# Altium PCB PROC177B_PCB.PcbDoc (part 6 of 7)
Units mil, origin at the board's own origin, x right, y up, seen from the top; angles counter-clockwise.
Board outline 4257.98 x 1561.15 mil, 4 copper layers (Top Layer, Int1 (GND), Int2 (PWR), Bottom Layer), stack 63.572 mil thick; 461 components, 307 nets, 1564 pads, 607 vias.
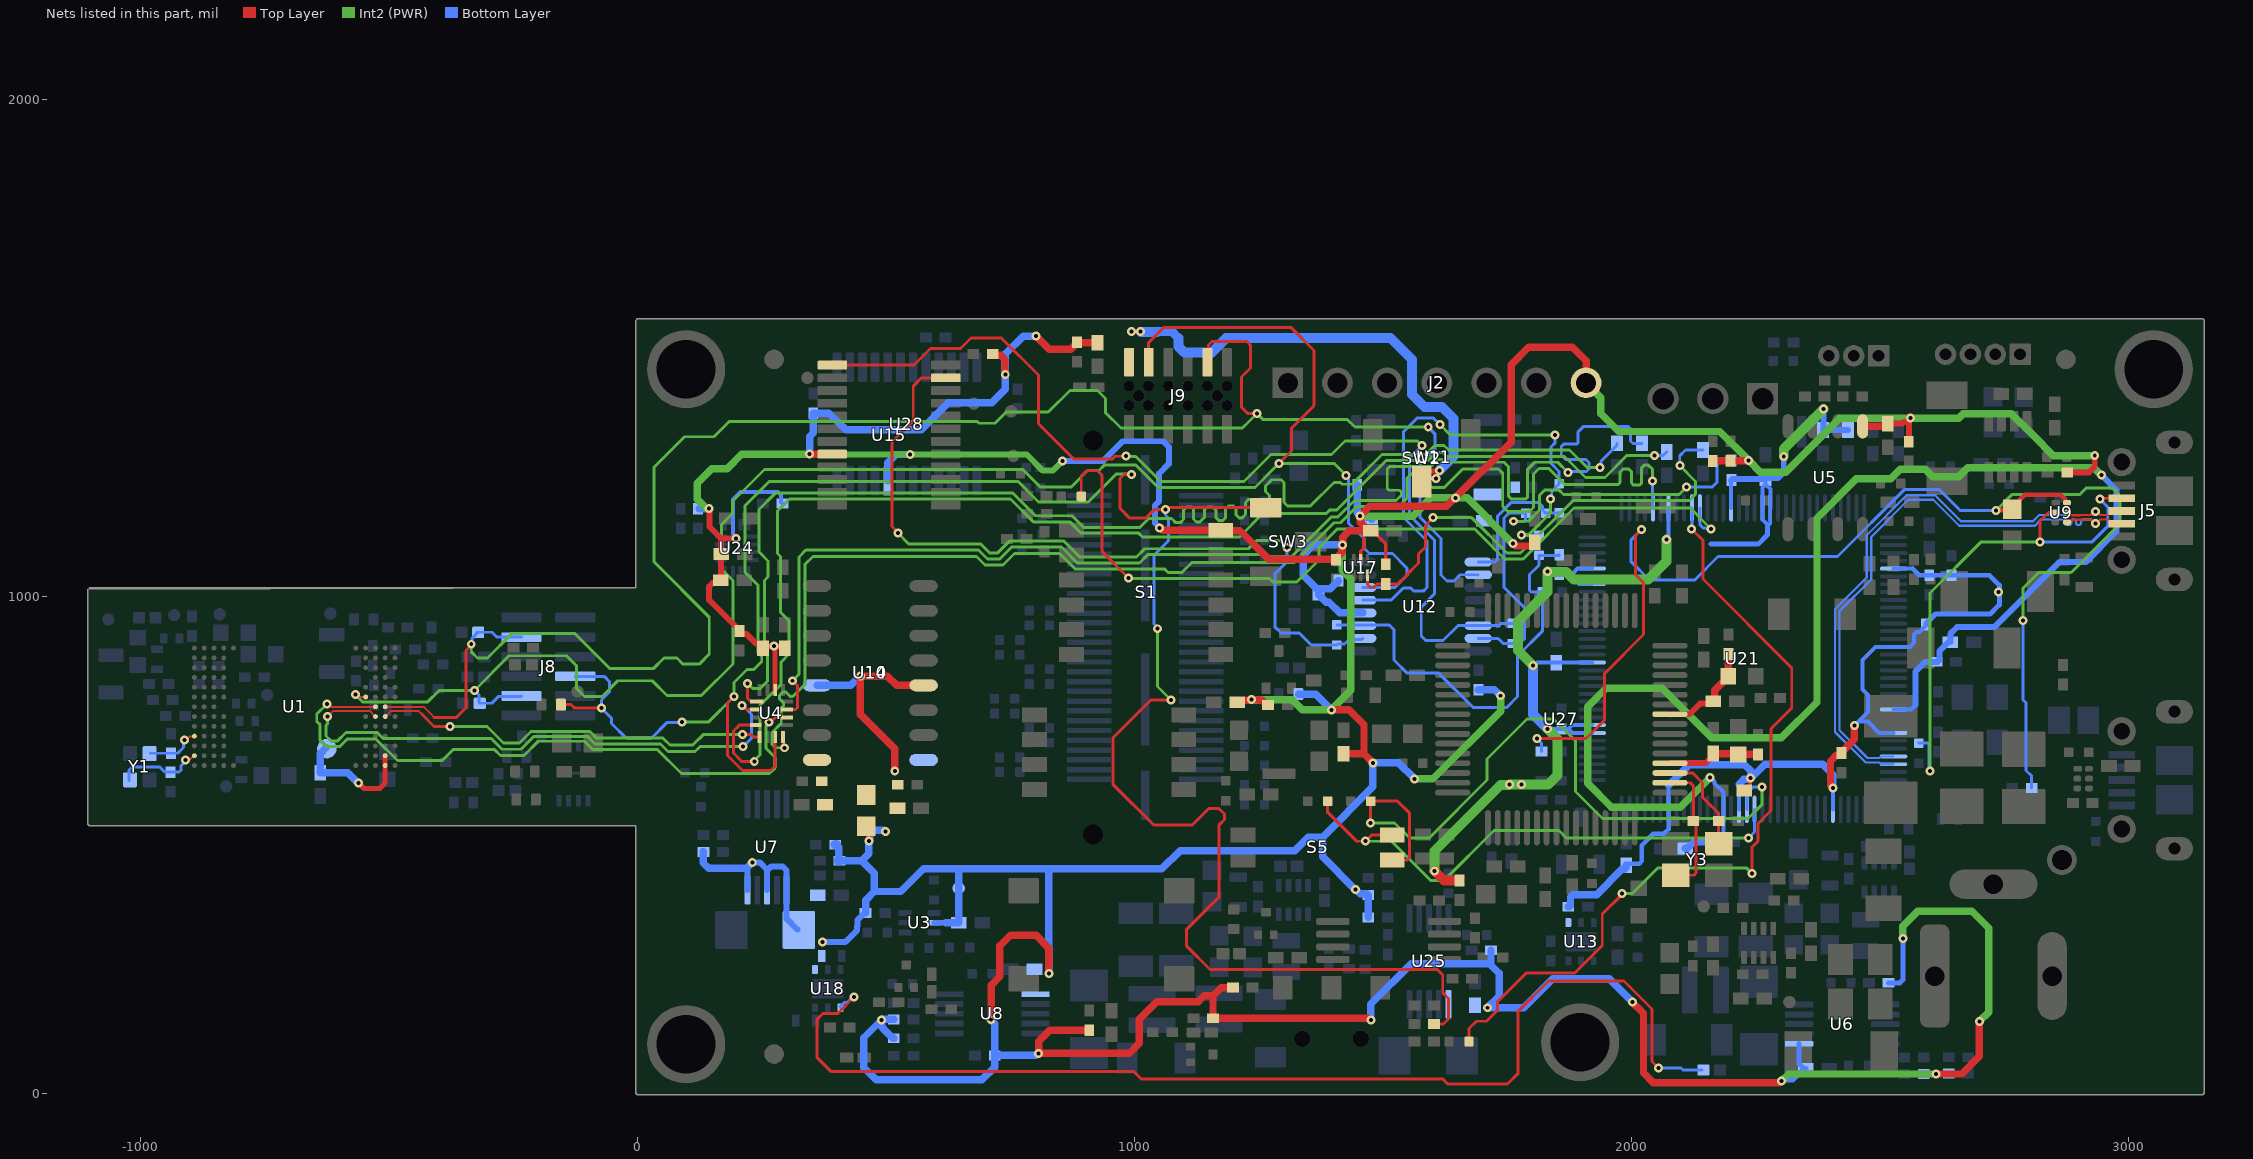
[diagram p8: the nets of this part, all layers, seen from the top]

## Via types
v1: diameter 18, hole 8, Top Layer to Bottom Layer, tented both sides, 603 vias
v2: diameter 19.68, hole 7.87, Top Layer to Bottom Layer, 4 vias

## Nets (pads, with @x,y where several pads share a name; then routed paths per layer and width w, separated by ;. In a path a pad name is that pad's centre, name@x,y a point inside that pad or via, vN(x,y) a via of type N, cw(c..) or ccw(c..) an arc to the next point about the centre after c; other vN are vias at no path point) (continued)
VCC_3V3: C2.1 C36.1 C38.2 C40.1 C41.1 C52.2 C56.1 C57.1 C58.1 C59.1 C65.1 C70.2 C91.1 C133.1 J2.7 R2.2 R5.2 R7.2 R8.2 R12.1 R14.2 R17.2 R22.2 R23.1 R27.2 R28.2 R54.2 R64.2 R65.1 R70.2 R90.1 R94.1 R97.2 R98.2 R99.2 R104.2 R105.2 R106.2 R107.2 R112.1 R115.1 R123.2 R129.1 R135.2 R136.2 R138.2 R142.1 R157.2 R161.2 R165.2 R172.2 R175.2 R198.2 R200.1 R204.2 R213.2 S1.12 TP9.1 U3.5 U4.14 U5.5 U6.6 U7.6 U7.8 U7.10 U8.6 U11.8 U12.12 U15.8 U17.5 U18.1 U24.14 U25.6 U28.8 | length 14993.9
  Top Layer w7: U17.5@1455.43,1073.44 1455.58,1073.59 1455.58,1090.64 1461.36,1096.42 1461.36,1121.59 C52.2@1471.65,1131.87 ; C52.2@1479.52,1131.87 1505.89,1105.51 R138.2@1505.89,1064.06
  Top Layer w10: v1(275.03,899.91) 275.03,897.74 277.72,895.04 U4.14@277.72,811.41
  Top Layer w12: v1(144.96,1176.13) 145.33,1175.76 145.33,1140.27 169.45,1116.14 169.45,1112.91 ; C2.1@168.17,1032 162.36,1026.19 151.58,1026.19 144.55,1019.16 144.55,992.49 201.14,935.9 201.88,935.9 205.72,932.06 205.72,928.61 209.57,924.77 209.57,924.28 219.61,924.28 238.82,905.07 247.28,905.07 253.09,899.26 C91.1@253.09,895.32 256.52,898.76 273.88,898.76 v1(275.03,899.91) 276.17,898.76 293.12,898.76 C40.1@296.84,895.04 ; C2.1@168.54,1032.37 168.54,1084.24 C56.1@168.91,1084.61 ; C56.1@168.61,1084.9 168.61,1116.98 ; 169.34,1116.25 v1(199.22,1116.25) ; R129.1@461,537.11 466.35,531.76 v1(466.35,507.67) ; C38.2@2515.6,1347 2544.07,1347 2547.33,1350.26 2551.54,1350.26 2559.6,1358.32 v1(2561.22,1358.32) ; R22.2@2558.1,1310.59 v1@2558.1,1361.03 ; R17.2@2876.71,1248.69 2920.4,1248.69 2932.2,1260.49 v1(2932.2,1282.82)
  Top Layer w15: v1(346.97,1285.74) U15.8@392.51,1285.74 ; v1@712.83,147.33 v1(712.26,147.91) 712.26,217.6 729.88,235.22 729.88,296.58 751.07,317.76 802.55,317.76 828.16,292.15 v1(828.16,240.96) ; R90.1@715.45,1487.02 717.79,1484.67 731.16,1484.67 739.95,1475.89 739.95,1446.18 v1(740.52,1445.61) ; v1(802.56,1523.02) 829.22,1496.36 872.14,1496.36 884.63,1508.84 R65.1@884.63,1510.81 ; v1(807.01,80.35) 807.29,80.08 989.71,80.08 1010.02,100.38 1010.02,148.61 1045.24,183.82 1128.29,183.82 1140.34,195.87 1158.41,195.87 ; v1@807.59,80.08 807.59,104.42 830.14,126.97 R165.2@909.27,126.97 ; R65.1@885.73,1509.71 R64.2@925.84,1509.71 ; v1(1051.21,1137.2) 1052.83,1137.2 1057.42,1132.62 S1.12@1173.96,1132.62 1174.5,1132.07 1212.67,1132.07 1270.56,1074.18 R123.2@1405.65,1074.18 ; R204.2@1198.46,212.89 1198.24,212.67 1175.21,212.67 1158.41,195.87 ; R70.2@1209.95,785.45 1215.17,790.67 1233.86,790.67 1235.22,792.03 v1(1236.03,792.03) 1236.6,791.46 1251.09,791.46 1252.03,790.51 1257.81,790.51 1267.22,781.11 R172.2@1269.19,781.11 ; v1(1396.67,771.33) 1432.05,771.33 1462.17,741.21 1462.17,683.25 ; R123.2@1405.65,1075.41 1418.2,1087.95 1418.2,1102.66 v1(1418.77,1103.23) 1419.35,1103.8 1419.35,1118.95 1432.27,1131.87 1471.65,1131.87 C52.2@1475.58,1131.87 C52.2@1479.52,1131.87 ; R213.2@1420.9,683.25 1462.17,683.25 ; C52.2@1471.37,1132.15 1454.8,1148.72 1454.8,1160.89 v1(1454.22,1161.46) 1473.26,1180.5 1627.94,1180.5 1645.12,1197.68 v1(1645.93,1197.68) 1757.99,1309.73 1757.99,1465.3 1793.89,1501.2 1880.85,1501.2 1908.83,1473.22 J2.7@1908.83,1429.21 ; v1(1476,147.6) 1475.19,147.6 1471.79,151 R28.2@1158.4,151 1158.4,195.87 ; v1(1480.15,664.54) 1480.15,665.28 1462.17,683.25 ; v1(1761.62,1105.8) 1762.43,1105.8 1767.27,1100.96 1801.12,1100.96 1805.44,1105.27 R99.2@1805.44,1108.25 ; v1(2002.56,183.22) 2002.56,182.48 2024.46,160.57 2024.46,41.17 2044.38,21.25 2297.75,21.25 2301.44,24.94 v1(2302.25,24.94) ; R98.2@2163.94,1272.17 2164.14,1272.37 2199.2,1272.37 R97.2@2199.4,1272.56 2235.53,1272.56 v1(2236.03,1273.05) ; U5.5@2465.27,1341.57 2511.29,1341.57 2515.6,1345.88 C38.2@2515.6,1347 ; v1(2613.08,38.77) 2664.71,38.77 2700.07,74.13 v1@2700.07,143.9
  Int2 (PWR) w12: v1(346.97,1285.74) 347.32,1285.39 v1(549.33,1285.39) 783.17,1285.39 816.06,1252.49 836.17,1252.49 v1(855.83,1272.16)
  Int2 (PWR) w15: v1(144.96,1176.13) 144.38,1176.7 138.95,1176.7 120.93,1194.72 120.93,1227.59 150.04,1256.7 181.26,1256.7 209.95,1285.39 346.61,1285.39 v1(346.97,1285.74) ; v1(1236.03,792.03) 1317.62,792.03 1338.31,771.33 v1(1396.67,771.33) 1435.71,810.38 1435.71,1034.68 1418.77,1051.62 v1(1418.77,1103.23) ; v1(1454.22,1161.46) 1454.75,1160.94 1560.14,1160.94 1596.87,1197.68 v1(1645.93,1197.68) 1669.74,1197.68 v1(1761.62,1105.8) ; v1(1564,632.6) 1600.94,632.6 1736.87,768.53 v1(1736.87,799.7) ; J2.7@1909.04,1429 1938.83,1399.2 1938.83,1367.43 1975.01,1331.25 2177.83,1331.25 v1(2236.03,1273.05) 2259.48,1249.6 2310.84,1249.6 2419.56,1358.32 2658.74,1358.32 2667.82,1367.4 2764.52,1367.4 2809.36,1322.56 2849.09,1282.82 v1(2932.2,1282.82) ; v1@2302.82,25.51 2316.08,38.77 v1(2613.08,38.77) ; v1(2546.09,311.49) 2546.09,336.04 2567.21,357.15 2576,365.94 2685.3,365.94 2718.74,332.51 2718.74,163.38 v1(2700.07,144.71)
  Bottom Layer w8: v1(199.22,1116.25) 199.22,1118.9 192.59,1125.53 192.59,1143.6 U24.14@192.53,1143.67 192.53,1194.13 208,1209.6 283.4,1209.6 289.25,1203.76 289.25,1189.74 R27.2@292.39,1186.6
  Bottom Layer w10: v1(2302.25,24.94) 2303.78,26.47 2324.25,26.47 C57.1@2347.21,49.43 ; U6.6@2337.55,99.67 2337.55,59.09 C57.1@2347.21,49.43 ; C57.1@2351.15,49.43 C57.1@2347.21,49.43 ; R94.1@2517.39,222.27 2540.23,222.27 2546.09,228.12 v1(2546.09,311.49)
  Bottom Layer w11: U3.5@597.22,343.01 621.03,343.01 ; R2.2@2588.39,39.05 2588.53,38.91 2612.94,38.91 v1(2613.08,38.77) 2613.6,39.3 2637.79,39.3 R14.2@2638.31,39.82
  Bottom Layer w12: 219.9,452.98 221.94,450.95 U7.10@221.94,408.58 ; v1(231.57,464.65) 231.61,464.6 246.57,464.6 261.31,449.86 ; U7.8@261.31,408.58 261.31,449.86 ; R200.1@322.65,329.06 300.74,350.97 300.74,408.51 U7.6@300.68,408.58 300.58,408.67 300.58,448.02 291.97,456.63 269.88,456.63 263.11,449.86 261.31,449.86 ; v1(372.96,304.01) 418.41,304.01 442.52,328.12 442.52,336.4 443.03,336.92 443.03,348.11 R54.2@457.7,362.78 ; v1(855.83,1272.16) 937.3,1272.16 976.83,1311.69 1058.06,1311.69 1069.59,1300.16 1069.59,1266.32 1050.06,1246.79 1050.06,1191.12 1041.71,1182.76 1041.71,1147.23 1051.21,1137.73 v1(1051.21,1137.2)
  Bottom Layer w15: R23.1@124.46,1176.13 v1(144.96,1176.13) ; R105.2@133.31,485.6 133.31,463.29 143.62,452.98 219.9,452.98 v1(231.57,464.65) ; v1(346.97,1285.74) 346.97,1321.08 354.19,1328.3 R12.1@354.19,1368.2 385.89,1368.2 419.42,1334.67 571.44,1334.67 625.77,1389 713.18,1389 740.52,1416.34 v1@740.52,1444.8 ; R112.1@400.36,500 405.32,495.05 R104.2@405.32,467.95 ; R104.2@407.13,467.79 451.82,467.79 ; R54.2@459.58,362.69 459.58,388.37 477.11,405.9 ; v1(466.35,507.67) 465.78,507.09 465.78,481.75 451.82,467.79 ; v1@467.91,510.04 467.91,520.03 476.7,528.82 496.36,528.82 498.87,526.31 v1(499.68,526.31) ; v1@493.91,148.6 R106.2@516.31,148.6 ; U28.8@504.26,1232.02 504.35,1232.11 504.35,1268.23 521.17,1285.05 548.99,1285.05 v1(549.33,1285.39) ; R107.2@516.31,110.6 513.97,112.94 512,112.94 494.84,130.11 494.84,130.96 492.08,133.72 492.08,147.23 492.89,148.04 492.08,148.04 v1(491.5,147.46) 456.26,112.22 456.26,51.38 480.76,26.87 693.19,26.87 719.06,52.74 719.06,75.9 R115.1@719.21,76.05 ; 621.03,343.01 646.62,343.01 C36.1@646.86,343.24 TP9.1@646.86,412.49 646.86,451.3 ; v1(712.26,147.91) 712.26,147.1 719.21,140.15 R115.1@719.21,76.05 ; v1(740.52,1445.61) 740.52,1487.24 776.3,1523.02 v1@801.75,1523.02 ; v1(807.01,80.35) 806.2,80.35 801.91,76.05 R115.1@719.21,76.05 ; v1(828.16,240.96) 828.16,451.3 ; R198.2@1330.67,803.03 1364.97,803.03 v1(1396.67,771.33) ; R7.2@1410.82,1031.52 1410.82,1029.55 1408.48,1027.21 1406.51,1027.21 1394.42,1015.11 1375.15,1015.11 C41.1@1370.83,1010.8 ; v1(1418.77,1103.23) 1360.3,1103.23 1339.76,1082.68 1339.76,1041.88 C41.1@1370.83,1010.8 ; v1@1443.77,409.59 1443.77,410.57 1378.81,475.53 1378.81,514.99 ; v1(1444.75,409.59) 1445.56,409.59 1454.09,401.06 1468.15,401.06 R135.2@1470.49,398.71 R136.2@1470.49,353.71 ; v1@1448.43,1168.06 R161.2@1448.43,1223.48 ; v1(1454.22,1161.46) 1455.03,1161.46 1457.64,1158.86 1473.57,1158.86 R175.2@1477.34,1155.09 ; U12.12@1459.67,966.28 1413.19,966.28 1391.78,987.69 1386.07,987.69 1370.83,1002.93 C41.1@1370.83,1006.86 C41.1@1370.83,1010.8 ; v1(1476,147.6) 1476,179.59 1557.09,260.68 1717.68,260.68 ; v1(1564,632.6) 1531.49,665.11 1480.72,665.11 v1(1480.15,664.54) 1480.15,616.33 1378.81,514.99 ; R8.2@1692.31,811.79 1724.66,811.79 1736.75,799.7 v1(1736.87,799.7) ; R142.1@1717.68,287.6 1717.68,260.68 ; v1(2002.56,183.22) 1955.41,230.36 1841.55,230.36 1783.24,172.06 v1(1710.51,172.06) 1734,195.55 1734,241 1717.68,257.32 1717.68,260.68 ; 451.82,467.79 477.11,442.5 477.11,405.9 ; 477.11,405.9 530.6,405.9 575.99,451.3 646.86,451.3 ; 646.86,451.3 828.16,451.3 ; 828.16,451.3 1055.61,451.3 1092.31,488 1322.9,488 1349.89,514.99 1378.81,514.99
  Bottom Layer w20: R112.1@398.71,500 R112.1@400.36,500 ; R104.2@405.32,467.95 405.48,467.79 R104.2@407.13,467.79
VCC_3V3_ENABLE: R9.2 U18.4 | length 2305.4
  Top Layer w5.9: v1(436.38,193.54) 403.47,160.63 374.06,160.63 361.47,148.03 361.47,72.31 389.65,44.13 998.7,44.13 1014.06,28.77 1620.65,28.77 1630.82,18.6 1751,18.6 1771.61,39.22 1771.61,164.02 1833.4,225.81 1985.35,225.81 2041.69,169.47 2041.69,63.91 v1(2055,50.6)
  Bottom Layer w5.9: U18.4@408.92,172.12 408.92,175.07 416.72,182.87 422.43,182.87 433.11,193.54 v1(436.38,193.54) ; v1(2055,50.6) 2100.04,50.6 2104,46.65 R9.2@2142.05,46.65
VCC_LVDS_3V3: C75.1 C88.1 C89.1 C90.1 R129.2 U10.4 U10.16 U14.4 U14.16 | length 450
  Top Layer w15: v1(518.25,648.7) 518.25,693.42 449,762.67 v1(449,839.6) 449.57,839.03 503.39,839.03 521.89,820.53 U14.4@576.39,820.53
  Bottom Layer w15: U10.4@361.83,820.53 429.93,820.53 v1(449,839.6)
VCC_SNSR_BRD: J9.2 SW2.2 | length 934.6
  Top Layer w10: SW2.2@1578.11,1239.99 1589.73,1251.61 1610.43,1251.61 1611.99,1253.17 v1(1614.16,1253.17)
  Bottom Layer w18: 1045.62,1531.38 1047.07,1532.83 1075.5,1532.83 1089,1519.34
  Bottom Layer w20: v1@1013.48,1531.38 1045.62,1531.38 ; 1089,1519.34 1089,1501.87 1100.72,1490.15 1156,1490.15 1184.94,1519.09 1515.31,1519.09 1558.56,1475.84 1558.56,1405.61 1583.57,1380.6 1618.92,1380.6 1642.21,1357.3 1642.21,1281.23 v1(1614.16,1253.17)
  other v1: 1607.04,1236.51 994.5,1532.55 1012.41,1532.46
VCC_XDS_3V3: C105.2 C106.2 C108.1 C113.2 C114.1 C115.1 C116.2 L7.1 R81.2 R82.2 R195.2 R196.2 R202.1 R231.2 R233.2 U13.1 U21.7 U21.8 U21.16 U21.26 U21.28 U21.39 U21.47 U21.51 U21.52 U21.69 U21.79 U21.90 U21.101 U21.113 U21.122 | length 4350.9
  Top Layer w8: C106.2@2227.06,608.87 2231,608.87 2238.81,616.68 2238.81,632.7 v1(2239.92,633.81)
  Top Layer w15: v1(2405.5,614.13) 2405.5,614.94 2400.66,619.79 2400.66,668.21 2412.43,679.98 2420.66,679.98 2420.66,681.94 C108.1@2423,684.29 ; C108.1@2423,686.26 2448.42,711.68 2448.42,739.3 v1(2448.99,739.87)
  Top Layer w20: v1(1603.84,447.36) 1622.96,428.24 L7.1@1654.28,428.24
  Int2 (PWR) w20: v1(1603.84,447.36) 1603.84,487.61 1736.7,620.46 1754.42,620.46 v1(1755,621.04) v1(1779.43,621.04) 1832.7,621.04 1851.4,639.73 1851.4,712.95 v1(1831.07,733.28) ; v1(1802,860.6) 1771.69,890.92 1771.69,948.9 1831,1008.21 v1(1831,1049.46) ; v1@1832.66,1048.6 1869,1048.6 1884.43,1033.17 2033.6,1033.17 2070.38,1069.96 v1(2070.38,1113.65) ; v1(2306.58,1280.6) 2306.58,1296.19 v1(2387,1376.6)
  Bottom Layer w8: v1(1802,860.6) 1804.7,860.6 1810.48,866.38 C116.2@1848.96,866.38 1849.16,866.58 U21.16@1921.25,866.58 ; v1(1831,1049.46) 1832.91,1047.54 1851.37,1047.54 R81.2@1855,1043.92 1875.22,1043.92 1881.28,1037.86 ; v1@1831.07,734.28 1832.14,733.2 C115.1@1859.31,733.2 1873.65,733.2 ; U21.7@1921.25,724.84 1882.01,724.84 1873.65,733.2 ; U21.8@1921.25,740.59 1881.03,740.59 1873.65,733.2 ; U21.26@1921.25,1024.06 1895.08,1024.06 1881.28,1037.86 ; U21.28@1921.25,1055.55 1921.18,1055.49 1891.89,1055.49 1881.28,1044.88 1881.28,1037.86 ; v1@2070.38,1110.94 v1(2070.38,1113.65) ; U21.122@2074.79,571.3 2074.79,619.39 ; U21.39@2074.79,1177.6 U21.39@2074.79,1177.6 v1@2074.85,1113.65 ; U21.47@2200.78,1177.6 2200.84,1177.66 R82.2@2200.84,1233.15 ; U21.113@2216.52,571.3 2216.52,621.85 ; C113.2@2269.89,1237.36 C113.2@2269.89,1225.06 ; U21.101@2405.5,571.3 v1(2405.5,614.13) ; v1(2448.99,739.87) 2456.67,747.55 ; U21.90@2527.55,724.84 U21.90@2527.55,724.84 2498.38,724.91 2475.74,747.55 2456.67,747.55 ; U21.69@2527.55,1055.55 2527.61,1055.49 2566.08,1055.49 ; C114.1@2592.89,943.06 2592.89,941.09 2579.47,927.68 2573.36,927.68 2568.67,923 2568.67,906.43 2560.38,898.14 2527.61,898.14 U21.79@2527.55,898.07 2527.48,898.01 2491.24,898.01 2465,871.77 2465,812.34 2476.25,801.09 2476.25,767.12 2456.67,747.55 ; C113.2@2269.89,1225.06 2263.77,1218.94 U21.51@2263.77,1177.6 2263.77,1154.1 2273.74,1144.13 2273.74,1140.08 2279.45,1145.79 2279.45,1177.54 U21.52@2279.52,1177.6 2279.52,1215.43 C113.2@2269.89,1225.06
  Bottom Layer w9: R233.2@1990,458.98 1993.02,462 2016.05,462 2021.32,467.27 2021.32,498.92 2044.21,521.81 2065.1,521.81 2074.79,531.5 U21.122@2074.79,571.3
  Bottom Layer w10: 2160.28,1104.6 2255,1104.6 2273.74,1123.35 2273.74,1140.08 ; 2566.08,1055.49 2579.46,1042.1 R231.2@2599.45,1042.1 R202.1@2644.1,1042.08 ; C114.1@2592.89,943.06 2592.89,945.03 2611.87,964.02 2721.7,964.02 2740.21,982.53 2740.21,1007.09 v1(2738.86,1008.44) ; R202.1@2644.1,1042.08 2720.09,1042.08 2740.14,1022.02 v1@2740.14,1008.8
  Bottom Layer w12: R82.2@2200.84,1233.15 R82.2@2201.44,1233.75 2203.25,1235.56 2268.08,1235.56 C113.2@2269.89,1237.36 2295.07,1237.36 2306.58,1248.88 v1(2306.58,1280.6) ; v1(2387,1376.6) 2386.25,1375.86 2386.25,1335.13 R196.2@2385.51,1334.38 R195.2@2436.08,1334.38
  Bottom Layer w15: C105.2@1873.33,375.07 1875.29,375.07 1877.64,377.41 1877.64,395.17 1882.11,399.65 1929.98,399.65 1981.07,450.73 1985.69,450.73 1989.32,454.36 R233.2@1989.32,458.98 ; 2074.79,619.39 2116.69,661.3 2227.67,661.3 2239.92,649.04 v1(2239.92,633.81) 2240.73,633.81 2268.85,661.93 2384.81,661.93 2405.5,641.23 v1(2405.5,614.13) ; 2216.52,621.85 2226.57,631.9 v1@2238.01,631.9
  Bottom Layer w20: v1(1802,860.6) 1802,762.35 v1(1831.07,733.28)
VDDC_1: C124.2 C125.2 C126.2 C127.1 U21.87 U21.115 | length 2991.6
  Int2 (PWR) w15: v1(2158.45,635.27) 2098.78,575.6 1960,575.6 1912,623.6 1912,777.6 1949,814.6 2062,814.6 2161.73,714.87 2301.44,714.87 2373.48,786.91 2373.48,1156.96 2452.41,1235.89 2521.83,1235.89 2541.33,1255.39 2591.44,1255.39 2606.16,1240.67 2658.48,1240.67 2676.36,1258.55 2930.04,1258.55 2944.59,1244 v1(2945.4,1244)
  Bottom Layer w8: v1(2158.45,635.27) 2161.53,632.2 2161.9,632.2 2166.14,627.96 2167.51,626.59 2167.51,623.28 2184.96,605.82 2184.96,571.36 U21.115@2185.03,571.3 2185.03,521.5 2168.98,505.45 C127.1@2167.01,505.45 ; U21.87@2527.55,772.09 2562.53,772.09 2571.96,781.52
  Bottom Layer w12: 2571.96,781.52 2571.96,848.93 2591.01,867.97 2613.74,867.97 C124.2@2613.79,868.02 2615.76,868.02 2619.6,871.87 2619.6,889.55 2637.58,907.54 C125.2@2641.52,907.54 ; C125.2@2642.35,907.54 C125.2@2641.52,907.54 ; v1(2945.4,1244) 2975.82,1213.58 2975.82,1130.57 2913.86,1068.6 2861.11,1068.6 2730.21,937.7 2655.19,937.7 2641.84,924.35 2641.84,907.85 C125.2@2641.52,907.54
  Bottom Layer w15: C126.2@2108.7,492.65 2112.64,492.65 2125.44,505.45 C127.1@2167.01,505.45
VPHY_FTDI: C141.1 C142.2 L2.2 U27.4 | length 188.4
  Top Layer w12: U27.4@2077.62,663.99 2149.07,663.99 2164.74,679.66 C142.2@2164.74,683.6
  Top Layer w15: C142.2@2164.74,683.6 2165.73,682.62 2213.76,682.62 C141.1@2214.74,681.63 L2.2@2254.74,681.63
VPLL_FTDI: C145.1 C146.2 L3.2 U27.9 | length 205.7
  Top Layer w12: U27.9@2077.62,762.41 2077.71,762.51 2116.86,762.51 2138.05,783.7 2160.07,783.7 C146.2@2164.91,788.54
  Top Layer w15: C146.2@2164.91,788.54 2167.7,791.33 2167.7,810.73 2194.83,837.86 C145.1@2194.83,838.85 2195.16,839.18 2195.16,883.16 L3.2@2195.5,883.5
VPP_1P7: C31.1 TP10.1 U1.A2 U1.B2 | length 258.9
  Top Layer w10: v1(-561,624.6) -549.62,613.22 -517.77,613.22 -506.87,624.12 U1.A2@-506.87,659.41 U1.B2@-506.87,679.09
  Bottom Layer w15: TP10.1@-625.34,695.6 -637.54,683.4 C31.1@-637.54,645.12 -582.33,645.12 -561.81,624.6 v1(-561,624.6)
XDS_DCA_RS232_RX: J8.9 J9.10 R74.1 U1.G2 U12.2 | length 3834.6
  Top Layer w4: U1.G2@-506.87,777.52 -429.69,777.52 -408.45,756.28
  Top Layer w5.9: -408.45,756.28 -363.46,756.28 -343.88,775.86 -343.88,890.5 -333.77,900.61 v1(-333.77,903.34) ; J9.10@1147.1,1470.81 1149.63,1473.34 1149.63,1505.14 1156.59,1512.1 1226.6,1512.1 1233.91,1504.79 1233.91,1459.04 1216.02,1441.15 1216.02,1379.94 1228.29,1367.67 v1(1246.71,1367.7)
  Int2 (PWR) w5.9: v1(-333.77,903.34) -333.77,888.06 -321.12,875.41 -301.29,875.41 -252.21,924.49 -124.86,924.49 -54.59,854.22 32.47,854.22 54.11,875.86 79.56,875.86 80,875.42 92.25,863.17 124.71,863.17 145.08,883.55 145.08,957.83 33.76,1069.15 33.76,1259.39 95.12,1320.75 154.73,1320.75 185.71,1351.73 683.76,1351.73 687.55,1347.94 719.93,1347.94 742.3,1370.31 826.85,1370.31 870.53,1413.99 925.88,1413.99 942.36,1397.51 942.36,1390.29 942.36,1368.96 973.16,1338.16 1217.33,1338.16 1230.56,1351.4 1230.56,1351.55 v1(1246.71,1367.7) 1246.82,1367.7 1259.39,1355.13 1429.05,1355.13 1443.98,1340.2 v1(1591.43,1340.2)
  Bottom Layer w5.9: v1(-333.77,903.34) -331.84,905.27 -331.84,915.28 -328.9,918.22 -328.9,919.07 -320.58,927.39 R74.1@-319.74,927.39 -291.79,927.39 -281.91,917.51 J8.9@-232.85,917.51 ; v1(1591.43,1340.2) 1604.71,1326.92 1604.71,1295.28 1574.8,1265.37 1574.8,1158.63 1617.2,1116.23 1617.2,1042.64 1629.37,1030.47 1643.28,1030.47 1655.86,1043.05 U12.2@1691.95,1043.05
XDS_DCA_RS232_TX: J8.3 J9.4 R73.1 U1.H4 U12.14 | length 3783.7
  Top Layer w4: v1(-566.73,801.79) -562.94,801.79 -558.36,797.2 U1.H4@-546.24,797.2
  Top Layer w5.9: J9.4@1028.99,1470.81 1028.99,1510.46 1058.7,1540.17 1315.86,1540.17 1361.57,1494.46 1361.57,1383.19 1316.22,1337.84 1316.22,1292.15 v1(1291.39,1267.33)
  Int2 (PWR) w5.9: v1(-566.73,801.79) -552.44,787.5 -421.21,787.5 -398.28,810.42 v1@-327.54,810.42 ; v1@-327.39,810.46 -257.74,880.12 -142.35,880.12 -121.63,859.39 -121.63,814.02 -105.92,798.31 -70.65,798.31 -39.13,829.84 30.5,829.84 60.22,800.11 80,800.11 128.97,800.11 192.7,863.85 192.7,1031.52 169.37,1054.85 169.37,1143.42 192.01,1166.06 192.01,1190.47 256.34,1254.8 775.78,1254.8 810.72,1219.86 873.32,1219.86 906.21,1252.75 928.91,1252.75 939.77,1263.61 1003.47,1263.61 1048.17,1218.91 1242.98,1218.91 v1(1291.39,1267.33) 1401.67,1267.33 v1(1425.82,1243.17)
  Bottom Layer w5.9: v1(-327.5,810.46) -318.27,801.23 -318.27,786.22 R73.1@-316.61,784.56 -292.54,784.56 -278.6,798.51 -233.74,798.51 J8.3@-232.85,799.4 ; v1(1425.82,1243.17) 1425.82,1239.89 1430.64,1235.08 1430.64,1147.4 1462.22,1115.82 1462.22,1096.45 1472.98,1085.7 1519.61,1085.7 1548.36,1056.95 1548.36,1041.74 1524.08,1017.46 U12.14@1459.67,1017.46
XDS_DCA_TCK: U1.F3 U4.2 | length 1166.3
  Top Layer w4: v1(-622.54,758.05) -611.15,769.44 -538.16,769.44 U1.F3@-526.56,757.83
  Top Layer w5.9: v1(211.18,780.02) 212.05,780.02 220.17,771.89 238.21,771.89 U4.2@238.35,772.04
  Int2 (PWR) w5.9: v1(-622.54,758.05) -622.54,743.46 -625.78,740.22 -625.78,718.66 -616.1,708.98 -602.46,708.98 -585.68,725.75 -522.79,725.75 -511.11,714.07 -293.92,714.07 -271.92,692.07 -233.59,692.07 -207.65,718.01 -100.01,718.01 -84.68,702.68 46.85,702.68 62.2,687.33 80,687.33 116.61,687.33 126.51,697.24 v1(212.97,697.24)
  Bottom Layer w5.9: v1(211.18,780.02) 212.29,780.02 229.95,762.36 229.95,714.21 v1(212.97,697.24)
XDS_DCA_TDI: U1.F2 U4.5 | length 818
  Top Layer w4: U1.F2@-506.87,757.83 -495.87,768.83 -439.23,768.83 -431.41,761.01
  Top Layer w5.9: -433,762.6 -408.42,738.02 v1(-376.72,738.02) ; v1(211.78,721.43) 229.29,721.43 233.8,716.92 U4.5@246.23,716.92
  Int2 (PWR) w5.9: v1(-376.72,738.02) -302.32,738.02 -269.05,704.76 -236.85,704.76 -213.7,727.91 -95.03,727.91 -81.45,714.33 52,714.33 65.9,700.43 80,700.43 111.84,700.43 132.85,721.43 v1(211.78,721.43)
XDS_DCA_TDO_SOP0: J8.6 R93.1 R203.1 SW3.1 U4.7 | length 4399
  Top Layer w5.9: R93.1@-149.33,781.9 -132.86,781.9 -125.63,774.66 v1(-71.66,774.66) ; v1(194.95,798.27) 181.76,785.09 181.76,679.5 212.13,649.13 268.46,649.13 277.72,658.4 277.72,684.65 277.7,699.54 U4.7@277.72,716.92 ; v1(994.32,1244.85) 979.35,1244.85 971.05,1236.55 971.05,1176.85 991.03,1156.88 1023.14,1156.88 1040.33,1174.07 v1(1062.71,1174.07) 1065.98,1174.07 1070.08,1178.16 SW3.1@1264.64,1178.16 ; v1(1074.06,791.39) 1033.15,791.39 957.68,715.92 957.68,620.84 1038.45,540.06 1117.21,540.06 1140.93,563.78 1140.93,563.83 1150.28,573.19 1169.71,573.19 1181.29,561.61 1181.29,550.54 1170.79,540.04 1170.79,395.4 1105.44,330.05 1105.44,295.97 1152.39,249.02 1609.63,249.02 1620.55,238.1 1620.55,202.2 1632.37,190.39 1632.37,149.43 1622.04,139.1 R203.1@1603.1,139.1
  Int2 (PWR) w5.9: v1(90.35,746.49) 143.17,746.49 v1(194.95,798.27) 194.95,826.22 221.24,852.51 234.76,852.51 250.61,868.35 250.61,879.11 243.29,886.43 243.29,1021.97 217.17,1048.08 217.17,1181.97 266.2,1231 765.92,1231 807.47,1189.45 907.36,1189.45 963.76,1245.86 993.31,1245.86 v1(994.32,1244.85) ; v1(1047.06,934.51) 1047,934.45 1047,818.45 v1(1074.06,791.39)
  Bottom Layer w5.9: J8.6@-124.58,838.77 -66.4,838.77 -55.62,827.98 -55.62,807.2 -71.66,791.16 v1(-71.66,774.66) -51.48,754.48 -51.48,744.03 -21.84,714.39 28.79,714.39 60.65,746.26 90.11,746.26 v1(90.35,746.49) ; v1(1047.06,934.51) 1047.06,936.98 1039.94,944.11 1039.94,1082.46 1069.16,1111.68 1069.16,1156.63 1062.65,1163.14 1062.65,1174 v1(1062.71,1174.07)
XDS_DCA_TMS: U1.G3 U4.10 | length 1327.8
  Top Layer w4: v1(-624.11,783.35) -620.33,783.35 -614.49,777.52 U1.G3@-526.56,777.52
  Top Layer w5.9: v1(265.04,746.39) 268.32,746.39 278.56,756.64 U4.10@300.99,756.64
  Int2 (PWR) w5.9: v1(-624.11,783.35) -644.57,762.89 -644.57,748.17 -637.6,741.2 -637.6,710.17 -625.41,697.98 -597.89,697.98 -583.54,712.32 -525.33,712.32 -482.39,669.39 -392.06,669.39 -370.29,691.16 -286.56,691.16 -275.09,679.69 -227.47,679.69 -199.06,708.11 -105.84,708.11 -89.41,691.68 40.41,691.68 89.05,643.05 265.66,643.05 277.64,655.02 277.64,675.58 258.99,694.23 258.99,721 259,740 265.04,746.04 v1(265.04,746.39)
XDS_NRST: R126.2 R138.1 U17.3 | length 995.9
  Top Layer w5.9: U17.3@1469.21,1041.94 1469.21,1023.39 1474.6,1018 1481.68,1018 1488.38,1024.69 R138.1@1505.89,1024.69 1529.78,1024.69 1536.31,1031.22 1537.84,1031.22 1548.36,1041.74 1548.36,1043.27 1571.68,1066.59 1571.68,1085.2 1585.69,1099.21 1585.69,1142.31 v1@1601.26,1157.87
  Int2 (PWR) w5.9: v1(1601.38,1158) 1678.74,1158 1749.81,1086.92 1777.13,1086.92 1882.93,1192.73 2116.76,1192.73 2129.25,1205.22 2129.25,1230.95 v1(2097.44,1262.77)
  Bottom Layer w5.9: v1(2097.44,1262.77) 2097.44,1282.3 2109.13,1293.99 R126.2@2144.09,1293.99
XDS_RS232_RX: R24.2 R188.1 U12.1 | length 276.9
  Bottom Layer w5.9: U12.1@1691.95,1068.64 1725.58,1068.64 1731.05,1074.12 1731.05,1161.48 1757.61,1188.04 1814,1188.04 1821.23,1180.81 1821.23,1173.35 R24.2@1827.63,1166.95 1828.12,1167.44 1854.23,1167.44 R188.1@1854.72,1167.93
XDS_RS232_TX: R26.2 R181.1 U12.13 | length 1095.9
  Int2 (PWR) w5.9: v1(1614.86,1345.37) 1635.88,1324.36 v1(1846.73,1324.36) ; v1(1778.62,1123.46) 1793.83,1123.46 1837.51,1167.14 v1(1837.51,1195.95)
  Bottom Layer w5.9: U12.13@1459.67,991.87 1460.21,992.41 1517.21,992.41 1541.31,1016.51 1554.1,1016.51 1554.15,1016.47 1556.22,1016.47 1562.65,1010.04 1581.35,1010.04 1588.74,1017.43 1588.74,1051.53 1588.8,1051.59 1588.8,1110.97 1550.78,1148.99 1550.78,1149.05 1541.67,1158.16 1541.67,1330.9 1568.92,1358.15 1602.08,1358.15 v1(1614.86,1345.37) ; v1(1778.62,1123.46) 1813.25,1123.46 R26.2@1814.16,1122.55 ; v1(1837.51,1195.95) 1839.82,1198.26 1839.82,1210.68 1854.7,1225.56 R181.1@1854.7,1226.06 1854.65,1226.11 1854.65,1241.29 1854.51,1241.43 1854.51,1251.04 1838.26,1267.28 1838.26,1300.19 1846.73,1308.65 v1(1846.73,1324.36)
XDS_SCL: R199.2 S5.3 U21.112 | length 1441.2
  Top Layer w5.9: v1(1475.08,543.86) 1475.41,544.19 1475.41,587.31 R199.2@1475.73,587.64 1529.68,587.64 1554.13,563.19 1554.13,474.32 1549.39,469.58 S5.3@1519,469.6
  Int2 (PWR) w5.9: v1(1475.08,543.86) 1523.66,543.86 1554,513.52 1593.35,513.52 1709.86,630.03 1709.86,672.73 1790.2,753.06 1843.6,753.06 1887.45,709.21 1887.45,607.3 1942.14,552.61 2234.53,552.61 2263.16,581.24 v1(2263.16,616.25)
  Bottom Layer w5.9: U21.112@2232.27,571.3 2232.27,603.23 2245.3,616.25 v1(2263.16,616.25)
XDS_SDA: R197.2 S5.4 U21.111 | length 1094.6
  Top Layer w5.9: R197.2@1389.18,587.6 1389.18,565.36 1447.48,507.05 v1(1465.27,507.05) 1477.61,519.39 1518.79,519.39 S5.4@1519,519.6
  Int2 (PWR) w5.9: v1@1465.53,507.05 1517.35,507.05 1595.99,428.41 1623.68,428.41 1723.62,528.35 1854.38,528.35 1869.22,513.51 v1(2235.77,513.51)
  Bottom Layer w5.9: v1(2235.77,513.51) 2248.02,525.75 U21.111@2248.02,571.3
XDS_SOP0: R43.1 U21.42 | length 1633.2
  Top Layer w5.9: R43.1@1673.46,104.1 1673.46,130.06 1688.23,144.83 1708.67,144.83 1730.89,167.05 1730.89,184.15 1788.29,241.55 1885.51,241.55 1941.46,297.51 1941.46,360.37 1981.48,400.4 v1(1981.48,401.94) ; v1(2121.16,1135.24) 2143.96,1112.45 2143.96,1034.4 2322.74,855.62 2322.74,774.85 2281.11,733.22 2281.11,568.67 2254.74,542.31 2254.74,507.09 2242.69,495.04 v1(2242.69,442.37)
  Int2 (PWR) w5.9: v1(1981.48,401.94) 2001.61,401.94 2052.49,452.82 2232.25,452.82 v1(2242.69,442.37)
  Bottom Layer w5.9: v1(2121.16,1135.24) 2121.66,1135.73 2121.66,1177.22 U21.42@2122.04,1177.6
XDS_SOP1: R67.1 U21.43 | length 1697.9
  Top Layer w5.9: R67.1@893.4,1200.7 893.4,1241.19 904.47,1252.26 926.14,1252.26 934.78,1243.62 934.78,1090.53 v1(988.66,1036.65)
  Int2 (PWR) w5.9: v1(988.66,1036.65) 989.56,1035.75 1272.04,1035.75 1279.62,1028.17 1326.6,1028.17 1371.46,1073.03 1371.46,1097.58 1388.92,1115.05 1388.92,1115.6 1408.23,1134.9 1685,1134.9 1744.88,1075.02 1782.39,1075.02 1884.59,1177.22 2118.45,1177.22 v1(2160.43,1135.24)
  Bottom Layer w5.9: U21.43@2137.78,1177.6 2137.78,1144.01 2144.23,1137.56 2158.11,1137.56 v1(2160.43,1135.24)
XDS_TCK: R122.2 U4.1 | length 2594.8
  Top Layer w5.9: v1(222.29,824.58) 222.29,794.3 227.82,788.77 239.33,788.77 U4.1@240.32,787.79
  Int2 (PWR) w5.9: v1(222.29,824.58) 232.3,814.57 247.59,814.57 262.51,829.48 262.51,884.04 255.92,890.63 255.92,1031.62 263.5,1039.19 263.5,1071.04 245.04,1089.49 245.04,1174.64 277.61,1207.2 756.06,1207.2 801.47,1161.8 874.82,1161.8 898.04,1138.57 1011.52,1138.57 1029.06,1156.12 1074.75,1156.12 1082.27,1148.6 1093.53,1148.6 1098.91,1153.98 1098.91,1172.95 1105.58,1179.62 1113.97,1179.62 1119.42,1174.16 1119.42,1155.1 1125.5,1149.02 1131.91,1149.02 1141.53,1158.64 1141.53,1173.96 1147.19,1179.62 1157.78,1179.62 1164.11,1173.29 1164.11,1158.42 1170,1152.54 1178.54,1152.54 1183.63,1157.62 1183.63,1175.55 1189.46,1181.38 1199.51,1181.38 1205.02,1175.87 1205.02,1163.35 1211.5,1156.88 1216.38,1156.88 1223.59,1164.08 1223.59,1188.46 1229.9,1194.78 1246.76,1194.78 1247.93,1193.61 1253.9,1187.64 1268.54,1187.64 1272,1191.1 1272,1202.77 1264,1210.77 1264,1221.6 1276.65,1234.25 1295.39,1234.25 1301.04,1228.61 1301.04,1189.03 1308.52,1181.54 1354.16,1181.54 1401.55,1228.94 1414.76,1228.94 1418.48,1225.22 1438.71,1225.22 1498.53,1285.04 1586.4,1285.04 1604.54,1303.18 1623.4,1303.18 1632.58,1294 1875.86,1294 1911.15,1258.71 v1(1936.75,1258.71)
  Bottom Layer w5.9: v1(1936.75,1258.71) 1939.06,1261.03 1939.06,1271.29 1971.24,1303.47 R122.2@1971.24,1307.41
XDS_TDI: R125.2 U4.4 | length 2628.4
  Top Layer w5.9: v1(235.58,667.08) 211.01,667.08 193.66,684.43 193.66,729.01 205.2,740.54 U4.4@238.35,740.54
  Int2 (PWR) w5.9: v1(235.58,667.08) 235.58,669.42 247.09,680.93 247.09,780.41 289.67,822.99 289.67,867.78 305.36,883.47 305.36,950.73 288.6,967.49 288.6,1079.59 282.09,1086.11 282.09,1171.15 306.24,1195.3 751.14,1195.3 796.92,1149.52 870.26,1149.52 893.11,1126.67 1009.02,1126.67 1016.44,1119.25 1211.83,1119.25 1259.24,1166.66 1387,1166.66 1393.28,1172.94 1406.65,1172.94 1506.86,1273.14 1591.32,1273.14 1606.85,1288.67 1620.88,1288.67 1628.28,1281.26 1865.45,1281.26 1907.76,1238.95 1946.97,1238.95 1990.75,1282.74 v1(2046.39,1282.74)
  Bottom Layer w5.9: v1(2046.39,1282.74) 2063.76,1282.74 R125.2@2071.2,1290.17
XDS_TDO: U4.8 U21.37 | length 2677.1
  Top Layer w5.9: U4.8@293.47,716.92 294.46,715.93 294.46,696.6 v1(296.02,695.04)
  Int2 (PWR) w5.9: v1(296.02,695.04) 278.31,695.04 271.26,702.09 271.26,725.99 289.86,744.59 289.86,774.97 294.92,780.03 294.92,784.92 286.37,793.47 286.37,800.54 293.37,807.54 298.37,807.54 300.35,805.55 307.95,797.95 312.84,797.95 338,823.12 338,1064.63 353.47,1080.09 682.42,1080.09 699.9,1062.61 735.96,1062.61 759,1085.65 849.99,1085.65 880.57,1055.07 1060.46,1055.07 1067.88,1047.65 1095.74,1047.65 1115.99,1067.9 1321.9,1067.9 1401.7,1147.7 1415.07,1147.7 1447.73,1180.36 1531.72,1180.36 1549.03,1197.67 1549.03,1237.89 1557.38,1246.23 1571.93,1246.23 1599.61,1218.56 1623.66,1218.56 1660.93,1255.83 1732.71,1255.83 1741.36,1247.18 1741.36,1180.13 1751.32,1170.17 1795.25,1170.17 1803.29,1178.22 1803.29,1245.61 1814.47,1256.79 1833.82,1256.79 1865.83,1224.77 1973.82,1224.77 1977.37,1228.32 1977.37,1249.54 1983.37,1255.54 1995.37,1255.54 2000.37,1250.54 2000.37,1227.53 2003.88,1224.02 2017.28,1224.02 2020.74,1227.47 2020.74,1258.19 2026.12,1263.58 2034.15,1263.58 2042.36,1255.38 v1(2042.36,1231.59)
  Bottom Layer w5.9: v1(2042.36,1231.59) 2042.92,1231.03 2042.92,1181.28 U21.37@2043.3,1180.89 ; U21.37@2042.94,1177.96 U21.37@2043.3,1177.6
XDS_TMS: R124.2 U4.11 | length 2588.8
  Top Layer w5.9: U4.11@301.34,772.04 318.68,772.04 322.95,776.31 322.95,819.09 312.6,829.43 v1(312.6,829.89)
  Int2 (PWR) w5.9: v1(312.6,829.89) 325.57,842.86 325.57,1079.09 339.24,1092.75 686.59,1092.75 704.7,1074.64 729.43,1074.64 753.59,1098.8 853.67,1098.8 885.5,1066.97 1010.54,1066.97 1027.12,1083.55 1260.83,1083.55 1264.58,1079.8 1316.97,1079.8 1396.77,1159.6 1410.14,1159.6 1442.8,1192.26 1526.79,1192.26 1537.13,1202.59 1537.13,1209.65 1533.67,1213.11 1512.43,1213.11 1508.97,1216.57 1508.97,1255.63 1514.58,1261.24 1596.25,1261.24 1610.32,1275.31 1617.41,1275.31 1623.35,1269.36 1743.72,1269.36 1753.26,1259.82 1753.26,1201.06 1759.13,1195.19 1787.26,1195.19 1790.72,1198.64 1790.72,1254.35 1805.73,1269.36 1851.96,1269.36 v1(1872.46,1248.87)
  Bottom Layer w5.9: v1(1872.46,1248.87) 1874.49,1250.9 1909.95,1250.9 1914.92,1255.87 1914.92,1268.68 1909,1274.6 1868.28,1274.6 1859.01,1283.87 1859.01,1300.9 1863.88,1305.76 1889.6,1305.76 1893.06,1309.22 1893.06,1330.58 1904.22,1341.74 1993.47,1341.74 1998.38,1336.82 1998.38,1312.35 2003.32,1307.41 R124.2@2021.22,1307.41
XDS_UARTA_RX: R24.1 R82.1 R127.2 U12.7 | length 982.5
  Int2 (PWR) w5.9: v1(1762.82,1150.73) 1792.63,1150.73 1815.19,1173.29 1815.19,1203.13 1825.79,1213.72 1829.9,1213.72 1830.07,1213.9 1854.09,1213.9 1863.26,1204.73 2096.49,1204.73 v1(2111.25,1219.5)
  Bottom Layer w5.9: U12.7@1691.95,915.1 1732.16,915.1 1742.28,904.98 R127.2@1760.74,904.98 1760.89,905.14 1775.97,905.14 1784.69,913.86 1784.69,976.95 1743.67,1017.98 1743.67,1157.27 1753.35,1166.95 R24.1@1787.28,1166.95 1787.28,1154.19 1783.82,1150.73 v1(1762.82,1150.73) ; v1(2111.25,1219.5) 2111.43,1219.67 2162.8,1219.67 2172.74,1229.6 2172.74,1265.19 2180.67,1273.12 R82.1@2201.44,1273.12
XDS_UARTA_RX_CAN_RX: R127.1 U12.6 U15.1 | length 2054.9
  Top Layer w5.9: U15.1@392.51,1464.88 556.96,1464.88 590.12,1498.04 650.27,1498.04 671.84,1519.6 732.4,1519.6 807.21,1444.79 807.21,1347.1 877.96,1276.35 956.1,1276.35 961.31,1281.56 v1(983.32,1281.56)
  Int2 (PWR) w5.9: v1(983.32,1281.56) 983.88,1281 1002.91,1281 1053.1,1230.81 1220.81,1230.81 1275.27,1285.28 1396.89,1285.28 1423.86,1312.24 1569.28,1312.24 1578.53,1302.99 v1(1578.96,1302.99)
  Bottom Layer w5.9: v1(1578.96,1302.99) 1553.57,1277.6 1553.57,1163.09 1562.68,1153.98 1562.68,1153.92 1603.69,1112.91 1603.69,1004.23 1577.29,977.83 1577.29,919.77 1586.45,910.6 1621,910.6 1651.09,940.69 U12.6@1691.95,940.69 1733.73,940.69 1738.38,945.33 R127.1@1760.74,945.33
XDS_UARTA_TX: R26.1 R81.1 R128.2 R190.1 U12.11 | length 854.6
  Bottom Layer w5.9: R128.2@1407.48,942.27 1459.67,942.27 1513.16,942.27 1522.8,932.63 1522.8,871.59 1549.27,845.11 1612.7,845.11 1681.32,776.49 1749.58,776.49 1771.15,798.05 1771.15,879.58 1820.89,929.32 R190.1@1820.89,1008.31 1798.7,1008.31 1795.18,1011.82 1795.18,1043.38 1814.16,1062.35 R26.1@1814.16,1082.2 1853.91,1082.2 R81.1@1855,1083.29
XDS_UARTA_TX_CAN_TX: R128.1 U12.10 U15.23 | length 1600
  Top Layer w5.9: v1(524.47,1127.09) 524.47,1128.31 512.69,1140.1 512.69,1309.89 555.41,1352.61 555.41,1422.48 572.22,1439.28 U15.23@620.85,1439.28
  Int2 (PWR) w5.9: v1(524.47,1127.09) 546.92,1104.65 691.52,1104.65 709.63,1086.54 724.5,1086.54 748.66,1110.7 858.59,1110.7 890.42,1078.87 1004.57,1078.87 1021.15,1095.45 1229.29,1095.45 1245.79,1111.95 1293.32,1111.95 v1(1307.51,1097.75)
  Bottom Layer w5.9: v1(1307.51,1097.75) 1307.51,1069.37 1282.8,1044.66 1282.8,1034.18 1282.8,938.44 1295.41,925.84 1331.97,925.84 1355.9,901.91 R128.1@1407.48,901.91 1409.34,903.77 1422.72,903.77 1431.79,912.84 1457.41,912.84 U12.10@1459.67,915.1
XDSET_1_DM: J5.2 U9.4 U21.93 | length 1212.7
  Top Layer w4.5: U9.4@2876.34,1148.57 2879.23,1148.57 2884.57,1153.91 2905.55,1153.91 2905.74,1154.09 2924.46,1154.09 2931.96,1146.59 v1(2933.85,1146.59) 2935.73,1146.59 2943.23,1154.09 2959.26,1154.09 J5.2@2961.9,1151.45 ; J5.2@2961.9,1151.42 2967.52,1145.79 J5.2@2986.22,1145.79
  Bottom Layer w4.5: U21.93@2527.55,677.6 2503.01,677.6 2501.32,675.91 2500.19,675.91 2498.56,674.28 2475.03,674.28 2418.88,730.44 2418.88,970.21 2482.38,1033.71 2482.38,1118.95 2557.24,1193.8 2607.43,1193.8 2659.48,1141.75 2811.88,1141.75 2824.23,1154.09 2873.19,1154.09 2875.82,1151.46 2875.82,1145.99 2878.5,1143.31 2882.39,1143.31 2885.03,1145.95 2885.03,1151.46 2887.66,1154.09 2891.89,1154.09 2894.53,1151.46 2894.53,1146.06 2897.17,1143.42 2901.91,1143.42 2904.55,1146.06 2904.55,1151.46 2907.19,1154.09 2924.46,1154.09 2931.96,1146.59 v1(2933.85,1146.59)
XDSET_1_DP: J5.3 U9.5 U21.94 | length 1212.1
  Top Layer w4.5: U9.5@2876.34,1168.25 2879.23,1168.25 2884.57,1162.91 2901.83,1162.91 2902.01,1163.09 2924.46,1163.09 2931.96,1170.59 v1(2933.85,1170.59) 2935.73,1170.59 2943.24,1163.09 2959.26,1163.09 J5.3@2961.9,1165.72 ; J5.3@2961.9,1165.76 2967.52,1171.38 J5.3@2986.22,1171.38
  Bottom Layer w4.5: U21.94@2527.55,661.85 2503.01,661.85 2501.16,663.7 2500.19,663.7 2498.61,665.28 2471.3,665.28 2409.88,726.71 2409.88,973.93 2473.38,1037.44 2473.38,1122.68 2553.51,1202.8 2611.16,1202.8 2618.05,1195.91 2663.21,1150.75 2808.16,1150.75 2820.5,1163.09 2886.11,1163.09 2924.46,1163.09 2931.96,1170.59 v1(2933.85,1170.59)
XDSET_1_ID: J5.4 R170.2 U9.2 | length 1031.7
  Top Layer w5.9: v1(2822,1109.32) 2822,1151.06 2839.19,1168.25 U9.2@2852.72,1168.25 ; v1(2942.77,1195.06) 2944.68,1196.97 J5.4@2986.22,1196.97
  Int2 (PWR) w5.9: v1(2600.8,648.36) 2600.8,1006.4 2703.71,1109.32 v1(2822,1109.32)
  Bottom Layer w5.9: R170.2@2578.12,704.39 2595.73,704.39 2599.18,700.93 2599.18,649.97 v1(2600.8,648.36) ; v1(2822,1109.32) 2927.19,1109.32 2958.34,1140.47 2958.34,1179.49 v1(2942.77,1195.06)
XDSET_1_VBUS: R1.1 R169.2 R236.2 U9.6 | length 2681.3
  Top Layer w5.9: v1(1810,713.46) 1909.04,713.46 1946.31,750.73 1946.31,844.52 2024.67,922.88 2024.67,1027.13 2008.06,1043.75 2008.06,1121.39 v1(2020.67,1134)
  Top Layer w9: v1(2734,1172.6) 2763.5,1172.6 2780.2,1189.3 2780.2,1192.67 2791.86,1204.33 2863.19,1204.33 2872.96,1194.56 2872.96,1189.34 2874.37,1187.94 U9.6@2876.34,1187.94
  Int2 (PWR) w5.9: v1(2734,1172.6) 2766.34,1204.94 2902.57,1204.94 2915.62,1218 2967.91,1218 2983.29,1202.62 2983.29,1145.86 2884.81,1047.38 2819.38,1047.38 2788.12,1016.12 v1(2788.12,951.52)
  Bottom Layer w5.9: v1(1810,713.46) 1819.31,704.11 R236.2@1819.31,687.6 ; v1(2020.67,1134) 1999,1112.33 1999,1070.15 2036.34,1032.81 2127.49,1032.81 2174.42,1079.74 2414.6,1079.74 2549.05,1214.19 2620.02,1214.19 2661.61,1172.6 v1(2734,1172.6) ; v1(2788.12,951.52) 2788.12,791.36 2793.79,785.7 2793.79,649.6 2805.39,638 R169.2@2805.39,614.32
XI_FTDI: C148.1 U27.2 Y3.1 | length 269.5
  Top Layer w5.9: U27.2@2077.62,624.62 2118.43,624.62 2124.6,618.44 C148.1@2124.6,547.51
  Top Layer w6: Y3.1@2089.38,438.61 2125.29,438.61 2130.02,443.34 2130.02,542.1 C148.1@2124.6,547.51
XO_FTDI: C147.1 U27.3 Y3.3 | length 210.2
  Top Layer w5.9: U27.3@2077.62,644.3 2077.9,644.02 2123.53,644.02 2143.35,624.19 2143.35,595.3 2175.75,562.91 2175.75,501.85 Y3.3@2176,501.6
XTALM: C33.2 U1.B10 Y1.1 | length 179.7
  Top Layer w4: v1(-909,670.6) -906.71,672.9 -898.5,672.9 -892.31,679.09 U1.B10@-890.73,679.09
  Bottom Layer w5.9: Y1.1@-1022.21,629.37 -1022.21,649.84 -1015.38,656.66 -960.8,656.66 -950.17,646.03 C33.2@-938.64,646.03 -921.87,646.03 -917.29,650.61 -917.29,659.61 -909,667.9 v1(-909,670.6)
XTALP: C32.2 U1.D10 Y1.3 | length 110.5
  Top Layer w4: v1(-911,711.03) -907.21,711.03 -900.89,717.35 -891.85,717.35 U1.D10@-890.73,718.46
  Bottom Layer w5.9: Y1.3@-978.9,684.49 -978.48,684.08 C32.2@-937.91,684.08 -924.38,684.08 -912.85,695.6 -912.85,709.17 v1(-911,711.03)
pads on no net: FID1.1 FID2.1 FID3.1 FID4.1 FID5.1 FID6.1 J6.14 J6.15 J6.16 J6.17 J6.19 J6.20 J6.21 J6.22 J6.23 J6.25 J6.27 J6.29 J6.31 J6.33 J6.35 J6.37 J6.39 J6.41 J6.43 J6.45 J6.47 J6.49 J6.MH1 J6.MH2 J9. S4.4 SW1. U11.1 U11.2 U13.2 U13.5 U13.7@1881.09,304.92 U13.7@1916.52,304.92 U14.9 U14.10 U14.11 U14.13 U14.14 U14.15 U18.2 U18.5 U18.7@365.62,210.5 U18.7@401.05,210.5 U21.2 U21.3 U21.4 U21.5 U21.6 U21.11 U21.12 U21.13 U21.14 U21.15 U21.18 U21.19 U21.20 U21.21 U21.22 U21.23 U21.24 U21.27 U21.29 U21.30 U21.31 U21.32 U21.41 U21.44 U21.45 U21.46 U21.49 U21.50 U21.53 U21.54 U21.56 U21.57 U21.65 U21.67 U21.71 U21.72 U21.73 U21.74 U21.75 U21.76 U21.77 U21.78 U21.81 U21.82 U21.83 U21.84 U21.85 U21.86 U21.91 U21.92 U21.97 U21.98 U21.99 U21.100 U21.102 U21.103 U21.104 U21.105 U21.106 U21.107 U21.108 U21.109 U21.110 U21.116 U21.117 U21.118 U21.119 U21.120 U21.121 U21.123 U21.124 U21.125 U21.126 U21.127 U21.128 U22.3 U23.3 U23.8 U26.6 U26.7 U27.21 U27.22 U27.23 U27.24 U27.26 U27.27 U27.28 U27.29 U27.30 U27.33 U27.38 U27.39 U27.40 U27.41 U27.43 U27.44 U27.46 U27.48 U27.52 U27.53 U27.57 U27.58 U27.60 U28.12 U28.16 U28.22

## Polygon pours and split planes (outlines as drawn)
GND on Top Layer "Top Layer-GND" (solid, remove dead copper, pour order 278): 12.42,13.72 3136.49,13.72 3136.49,1542.71 12.42,1542.71 12.42,1006.87 -1094.56,1006.87 -1094.56,553.75 12.42,553.75
RADAR_1V8 on Top Layer "NONET_L08_P-001" (solid, remove dead copper, pour order 106): -851.07,925.87 -877.12,925.87 -896.76,904.31 -896.76,890.73 -892.91,886.88 -880.78,886.88 -876.87,882.97 -876.87,873.14 -872.4,868.67 -814.72,868.67 -801.26,882.12 -801.26,919.57 -807.57,925.88
RADAR_1P2_RF on Top Layer "NONET_L08_P-001" (solid, remove dead copper, pour order 45): -904.83,874.78 -907.47,877.42 -944.97,877.42 -959.14,863.25 -959.14,839.78 -951.64,832.28 -932.33,832.28 -922.61,842 -911.64,852.98 -899.55,852.98 -896.36,856.17 -896.36,866.45 -899.41,869.5
RADAR_1V8 on Top Layer "Top Layer-RADAR_1V8" (solid, remove dead copper, pour order 251): 21 vertices, not listed, extent 81,339.6 126.11,931.27
FTDI_3V3 on Top Layer "NONET_L-01_P-001" (solid, remove dead copper, pour order 263): 17 vertices, not listed, extent 1825.59,931.87 1957.2,1137.2
FTDI_3V3 on Top Layer "NONET_L-01_P-001" (solid, remove dead copper, pour order 252): 58 vertices, not listed, extent 1309.86,254.7 1860.15,606.54
RADAR_1V2 on Top Layer "NONET_L-01_P-001" (solid, remove dead copper, pour order 250): 87.66,975.23 127.18,975.23 127.18,936.32 87.66,936.32
FTDI_VBUS on Top Layer "NONET_L08_P-001" (solid, remove dead copper, pour order 19): 17 vertices, not listed, extent 2847.98,676.1 2957.41,842.05
VCC_SNSR_BRD on Top Layer "NONET_L08_P-001" (solid, remove dead copper, pour order 276): 1560.39,1271.49 1617.15,1271.49 1628,1260.64 1628,1225.36 1601.8,1199.17 1558.42,1199.17 1558.42,1269.52
5V_IN_USB on Top Layer "NONET_L08_P-001" (solid, remove dead copper, pour order 167): 40 vertices, not listed, extent 2253.3,319.12 2784.7,1131.72
NetD1_2 on Top Layer "NONET_L08_P-001" (solid, remove dead copper, pour order 164): 2854.58,1050.84 2794.46,1050.84 2792.23,1048.61 2792.23,970.4 2796.24,966.39 2874.86,966.39 2881.83,973.36 2881.83,1046.03 2859.39,1046.03
NetC158_1 on Top Layer "NONET_L08_P-001" (solid, remove dead copper, pour order 23): 2912.6,685.99 2912.6,699.67 2914.16,701.23 2959.55,701.23 2963.85,696.92 2963.85,687.74 2976.48,675.11 2976.48,645.81 2917.88,645.81 2916.82,646.87 2914.02,648.03 2912.6,649.45
VCC_SNSR_BRD on Top Layer "NONET_L08_P-001" (solid, remove dead copper, pour order 277): 989.62,1441.87 974.48,1441.87 961.8,1454.56 961.8,1529.3 973.42,1540.93 1018.5,1540.93 1023.39,1536.03 1023.39,1524 1005.44,1506.05 1005.44,1449 998.89,1442.45
FTDI_3V3 on Top Layer "NONET_L-01_P-001" (solid, remove dead copper, pour order 255): 18 vertices, not listed, extent 1657.7,934.35 1746.87,1103.9
FTDI_3V3 on Top Layer "NONET_L-01_P-001" (solid, remove dead copper, pour order 254): 19 vertices, not listed, extent 1535.03,701.82 1677.18,794.5
CONN_5V on Top Layer "NONET_L08_P-001" (solid, remove dead copper, pour order 242): 26 vertices, not listed, extent 981.81,1190.53 1379,1277.31
5V_IN on Top Layer "NONET_L08_P-001" (solid, remove dead copper, pour order 153): 30 vertices, not listed, extent 2049.9,258.77 2252.62,374.25
5V_REG on Top Layer "NONET_L08_P-001" (solid, remove dead copper, pour order 168): 24 vertices, not listed, extent 2250.21,39.88 2389.27,345.48
RADAR_1V2 on Top Layer "NONET_L08_P-001" (solid, remove dead copper, pour order 237): 139,632.46 150.14,643.6 197,643.6 203,637.6 203,605.6 192,594.6 149,594.6 139,604.6
FTDI_3V3 on Top Layer "NONET_L-01_P-001" (solid, remove dead copper, pour order 253): 18 vertices, not listed, extent 1666.17,217.26 1768.19,284.5
RADAR_3V3 on Top Layer "NONET_L08_P-001" (solid, remove dead copper, pour order 244): 28 vertices, not listed, extent 26.09,268.36 832.19,583.24
VCC_3V3 on Top Layer "NONET_L08_P-001" (solid, remove dead copper, pour order 224): 515.54,534.4 515.54,518.84 505.68,509.35 487.77,509.35 479.7,517.42 442.3,517.42 442.3,556.79 493.15,556.79
GND on Top Layer "NONET_L08_P-001" (solid, remove dead copper, pour order 275): 1178.6,1504.75 1215.52,1504.75 1219.34,1500.93 1219.34,1467.2 1199.01,1446.87 1178.6,1446.87 1176.63,1448.84 1176.63,1502.78
GND on Top Layer "NONET_L08_P-001" (solid, remove dead copper, pour order 219): 2273.13,928.73 2341.45,928.73 2352,939.27 2352,997.6 2401.22,1046.82 2538.12,1046.82 2552.97,1061.67 2610.67,1061.67 2615.54,1066.54 2615.54,1094.25 2319.64,1094.25 2259,1033.6 2259,942.86
GND on Top Layer "NONET_L08_P-001" (solid, remove dead copper, pour order 169): 18 vertices, not listed, extent 2035.07,149.47 2236.12,287.37
RADAR_3V3 on Top Layer "NONET_L-01_P-001" (solid, remove dead copper, pour order 271): -261.3,874.25 -234.08,874.25 -232.29,872.46 -232.29,838.55 -230.17,836.44 -173.78,836.44 -167.58,830.24 -167.58,815.41 -174.76,808.24 -240.93,808.24 -262.77,830.08 -262.77,872.77 -261.34,874.2
FTDI_3V3 on Top Layer "NONET_L-01_P-001" (solid, remove dead copper, pour order 259): 2017.22,1092.27 2050.33,1092.27 2058.81,1083.79 2058.81,1032.6 2058.58,1032.37 2031.62,1032.37 2011.41,1052.58 2011.41,1084.7
NetD2_2 on Top Layer "NONET_L08_P-001" (solid, remove dead copper, pour order 162): 2477.02,300.57 2477.02,59.93 2498.37,38.58 2561.26,38.58 2578.86,56.18 2578.86,135.56 2560.39,154.03 2560.39,290.5 2549.89,301
NetC48_1 on Top Layer "NONET_L08_P-001" (solid, remove dead copper, pour order 158): 19 vertices, not listed, extent 2396.75,148.05 2836.67,638.99
RADAR_1V_RF_OUT on Top Layer "NONET_L08_P-001" (solid, remove dead copper, pour order 35): -796.32,864.9 -792.98,861.56 -792.98,831.54 -796.09,828.43 -806.6,828.47 -806.75,828.32 -819.75,828.32 -820.24,828.8 -823.44,835.98 -823.44,846.75 -819.46,850.73 -819.46,859.56 -814.12,864.9
NetF1_2 on Top Layer "NONET_L08_P-001" (solid, remove dead copper, pour order 154): 2580.52,137.3 2590.03,127.79 2630.47,127.79 2684.66,181.99 2684.66,337.22 2607.77,414.11 2486.46,414.11 2471.31,398.71 2471.31,346.58 2553.46,346.58 2580.52,319.53
VCC_LVDS_3V3 on Top Layer "NONET_L08_P-001" (solid, remove dead copper, pour order 223): 24 vertices, not listed, extent 333.28,561.74 539.39,682.34
GND on Top Layer "NONET_L08_P-001" (solid, remove dead copper, pour order 170): 2325.84,445.69 2333.15,452.99 2374.89,452.99 2387,441.07 2387,327.11 2373.03,313.14 2330.46,313.14 2314.87,328.73 2314.87,401.33 2325.84,412.31
USB_5V on Top Layer "NONET_L08_P-001" (solid, remove dead copper, pour order 165): 18 vertices, not listed, extent 2860.99,1052.25 3012.8,1128.56
NetD12_2 on Top Layer "NONET_L08_P-001" (solid, remove dead copper, pour order 163): 2837.86,854.68 2842.8,849.74 2878.33,849.74 2897,868.41 2897,930 2880.65,946.35 2737.04,946.35 2728.05,937.36 2728.05,854.68
GND on Top Layer "NONET_L08_P-001" (solid, remove dead copper, pour order 149): -523.53,933.72 -570.31,933.72 -574.19,929.84 -574.19,896.06 -567.8,889.67 -524.9,889.67 -519.19,895.38 -519.88,896.06 -519.88,925.96
GND on Top Layer "NONET_L08_P-001" (solid, remove dead copper, pour order 104): -107.83,723.62 -63.82,723.62 -63.82,642.93 -75.42,631.32 -113.28,631.32 -119.64,637.68 -119.64,667.8 -112.18,675.26 -112.18,719.27
RADAR_3V3 on Top Layer "NONET_L08_P-001" (solid, remove dead copper, pour order 24): -129.84,737.74 -153.83,761.73 -267.67,761.73 -267.67,724.55 -192.83,724.55 -171.65,703.24 -171.65,675.06 -165.66,669.08 -165.66,624.35 -167.57,622.44 -167.57,604.42 -129.84,604.42
GND on Bottom Layer "Bottom Layer-GND" (solid, remove dead copper, pour order 269): 12.42,13.72 3136.49,13.72 3136.49,1542.71 12.42,1542.71 12.42,1013.78 -1102.34,1013.78 -1102.34,541.34 -0.06,541.34 12.42,528.86
VCC_XDS_3V3 on Bottom Layer "NONET_L08_P-001" (solid, remove dead copper, pour order 228): 67 vertices, not listed, extent 1738.34,333.65 2417.32,673.9
NetJ10_6 on Bottom Layer "NETJ10_6_L04_P110" (solid, remove dead copper, pour order 110): 23 vertices, not listed, extent 2920.88,465.77 3131.8,791.4
FTDI_VBUS on Bottom Layer "NONET_L08_P-001" (solid, remove dead copper, pour order 159): 2893.69,834.22 2904.39,844.92 2938.74,844.92 2945.93,837.72 2945.93,716.07 2970.09,691.91 3012.8,691.91 3012.8,673.41 2916.48,673.41 2893.69,696.2 2893.69,794.92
